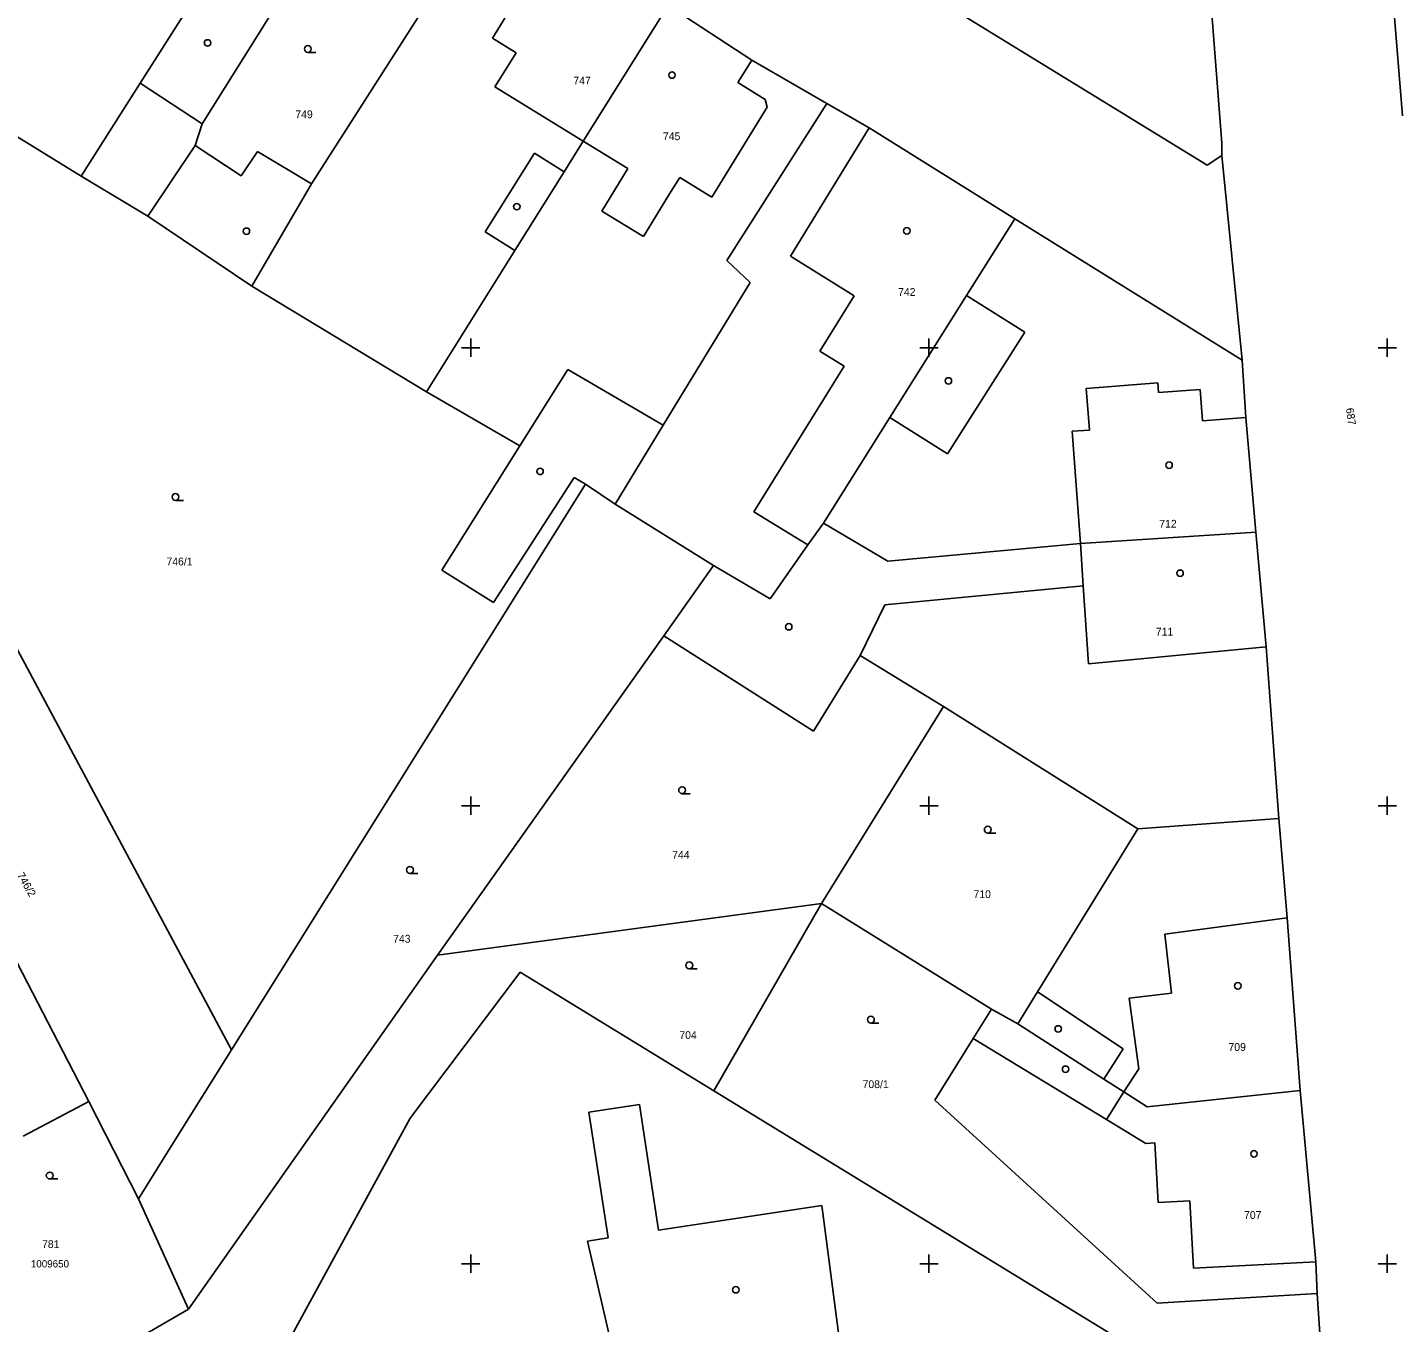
# Model space of a CAD drawing. Extents: x -702257 to -701487, y -1009871 to -1008841.
# Drawn here: x -701799.2 to -701724.3, y -1009653.2 to -1009582.5 of the extents above; entities that cross this region are included whole.
import ezdxf

# ---------------------------------------------------------------- set-up
doc = ezdxf.new("R2010")
doc.units = 0
for name, color, linetype in [('Z_hektometricka_sit', 7, 'Continuous'), ('Z_hektometricka_sit_popis', 7, 'Continuous'), ('Z_katastr_cisla_pozemkova', 7, 'Continuous'), ('Z_katastr_cisla_stavebni', 7, 'Continuous'), ('Z_katastr_hranice', 7, 'Continuous'), ('Z_katastr_vnitrni_kresba', 7, 'Continuous'), ('Z_katastr_znacky_budov', 7, 'Continuous'), ('Z_katastr_znacky_kultur', 7, 'Continuous')]:
    doc.layers.add(name, color=color, linetype=linetype)

msp = doc.modelspace()

# ---------------------------------------------------------------- linework, layer by layer
at = {"layer": 'Z_hektometricka_sit'}
for p, q in [((-701775, -1009599.5), (-701775, -1009600.5)), ((-701775, -1009599.5), (-701775, -1009600.5)), ((-701750, -1009599.5), (-701750, -1009600.5)), ((-701750, -1009599.5), (-701750, -1009600.5)), ((-701725, -1009599.5), (-701725, -1009600.5)), ((-701725, -1009599.5), (-701725, -1009600.5)), ((-701775.5, -1009600), (-701774.5, -1009600)), ((-701775.5, -1009600), (-701774.5, -1009600)), ((-701750.5, -1009600), (-701749.5, -1009600)), ((-701750.5, -1009600), (-701749.5, -1009600)), ((-701725.5, -1009600), (-701724.5, -1009600)), ((-701725.5, -1009600), (-701724.5, -1009600)), ((-701775, -1009624.5), (-701775, -1009625.5)), ((-701775, -1009624.5), (-701775, -1009625.5)), ((-701750, -1009624.5), (-701750, -1009625.5)), ((-701750, -1009624.5), (-701750, -1009625.5)), ((-701725, -1009624.5), (-701725, -1009625.5)), ((-701725, -1009624.5), (-701725, -1009625.5)), ((-701775.5, -1009625), (-701774.5, -1009625)), ((-701775.5, -1009625), (-701774.5, -1009625)), ((-701750.5, -1009625), (-701749.5, -1009625)), ((-701750.5, -1009625), (-701749.5, -1009625)), ((-701725.5, -1009625), (-701724.5, -1009625)), ((-701725.5, -1009625), (-701724.5, -1009625)), ((-701775, -1009649.5), (-701775, -1009650.5)), ((-701775, -1009649.5), (-701775, -1009650.5)), ((-701750, -1009649.5), (-701750, -1009650.5)), ((-701750, -1009649.5), (-701750, -1009650.5)), ((-701725, -1009649.5), (-701725, -1009650.5)), ((-701725, -1009649.5), (-701725, -1009650.5)), ((-701775.5, -1009650), (-701774.5, -1009650)), ((-701775.5, -1009650), (-701774.5, -1009650)), ((-701750.5, -1009650), (-701749.5, -1009650)), ((-701750.5, -1009650), (-701749.5, -1009650)), ((-701725.5, -1009650), (-701724.5, -1009650)), ((-701725.5, -1009650), (-701724.5, -1009650))]:
    msp.add_line(p, q, dxfattribs=at)
at = {"layer": 'Z_katastr_hranice'}
for p, q in [((-701725.75, -1009567.95), (-701724.17, -1009587.34)), ((-701773.82, -1009575.61), (-701783.68, -1009591.06)), ((-701787.72, -1009577.2), (-701793.03, -1009585.56)), ((-701734.87, -1009577.75), (-701734.02, -1009588.83)), ((-701754.01, -1009578.25), (-701734.82, -1009590.03)), ((-701789.65, -1009587.78), (-701785.11, -1009580.52)), ((-701764.23, -1009581.32), (-701768.86, -1009588.72)), ((-701759.67, -1009584.3), (-701764.23, -1009581.32)), ((-701755.58, -1009586.66), (-701759.67, -1009584.3)), ((-701793.03, -1009585.56), (-701796.25, -1009590.63)), ((-701803.43, -1009586.21), (-701796.25, -1009590.63)), ((-701755.58, -1009586.66), (-701761.02, -1009595.24)), ((-701753.27, -1009587.99), (-701755.58, -1009586.66)), ((-701790.03, -1009588.96), (-701789.65, -1009587.78)), ((-701745.32, -1009592.96), (-701753.27, -1009587.99)), ((-701787.53, -1009590.62), (-701790.03, -1009588.96)), ((-701786.64, -1009589.28), (-701787.53, -1009590.62)), ((-701783.68, -1009591.06), (-701786.64, -1009589.28)), ((-701768.86, -1009588.72), (-701769.9, -1009590.39)), ((-701734.02, -1009588.83), (-701734.02, -1009589.5)), ((-701734.82, -1009590.03), (-701734.02, -1009589.5)), ((-701734.02, -1009589.5), (-701732.92, -1009600.67)), ((-701796.25, -1009590.63), (-701792.62, -1009592.81)), ((-701769.9, -1009590.39), (-701772.59, -1009594.69)), ((-701783.68, -1009591.06), (-701786.94, -1009596.63)), ((-701792.62, -1009592.81), (-701786.94, -1009596.63)), ((-701745.32, -1009592.96), (-701747.95, -1009597.14)), ((-701732.92, -1009600.67), (-701745.32, -1009592.96)), ((-701772.59, -1009594.69), (-701777.42, -1009602.4)), ((-701761.02, -1009595.24), (-701759.75, -1009596.44)), ((-701786.94, -1009596.63), (-701777.42, -1009602.4)), ((-701759.75, -1009596.44), (-701764.5, -1009604.23)), ((-701747.95, -1009597.14), (-701752.14, -1009603.81)), ((-701732.92, -1009600.67), (-701732.71, -1009603.81)), ((-701777.42, -1009602.4), (-701772.32, -1009605.36)), ((-701764.5, -1009604.23), (-701767.12, -1009608.53)), ((-701752.14, -1009603.81), (-701755.76, -1009609.57)), ((-701732.71, -1009603.81), (-701732.17, -1009610.07)), ((-701772.32, -1009605.36), (-701776.57, -1009612.14)), ((-701773.75, -1009613.9), (-701769.35, -1009607.08)), ((-701769.35, -1009607.08), (-701768.73, -1009607.44)), ((-701768.73, -1009607.44), (-701788.05, -1009638.33)), ((-701767.12, -1009608.53), (-701768.73, -1009607.44)), ((-701767.12, -1009608.53), (-701761.75, -1009611.88)), ((-701755.76, -1009609.57), (-701756.6, -1009610.76)), ((-701752.25, -1009611.65), (-701755.76, -1009609.57)), ((-701732.17, -1009610.07), (-701741.73, -1009610.69)), ((-701732.17, -1009610.07), (-701731.61, -1009616.32)), ((-701756.6, -1009610.76), (-701758.67, -1009613.71)), ((-701741.73, -1009610.69), (-701752.25, -1009611.65)), ((-701776.57, -1009612.14), (-701773.75, -1009613.9)), ((-701761.75, -1009611.88), (-701764.47, -1009615.72)), ((-701758.67, -1009613.71), (-701761.75, -1009611.88)), ((-701801.79, -1009612.64), (-701788.05, -1009638.33)), ((-701776.81, -1009633.16), (-701764.47, -1009615.72)), ((-701764.47, -1009615.72), (-701756.29, -1009620.92)), ((-701756.29, -1009620.92), (-701753.76, -1009616.79)), ((-701753.76, -1009616.79), (-701749.21, -1009619.59)), ((-701731.61, -1009616.32), (-701730.91, -1009625.7)), ((-701749.21, -1009619.59), (-701755.86, -1009630.34)), ((-701738.6, -1009626.25), (-701749.21, -1009619.59)), ((-701730.91, -1009625.7), (-701738.6, -1009626.25)), ((-701730.91, -1009625.7), (-701730.45, -1009631.11)), ((-701738.6, -1009626.25), (-701744.07, -1009635.15)), ((-701795.84, -1009641.14), (-701801.48, -1009630.24)), ((-701755.86, -1009630.34), (-701776.81, -1009633.16)), ((-701761.73, -1009640.56), (-701755.86, -1009630.34)), ((-701755.86, -1009630.34), (-701746.58, -1009636.11)), ((-701730.45, -1009631.11), (-701729.74, -1009640.54)), ((-701776.81, -1009633.16), (-701790.39, -1009652.48)), ((-701778.31, -1009642.06), (-701772.31, -1009634.08)), ((-701772.31, -1009634.08), (-701761.73, -1009640.56)), ((-701744.07, -1009635.15), (-701745.15, -1009636.91)), ((-701746.58, -1009636.11), (-701747.58, -1009637.71)), ((-701745.15, -1009636.91), (-701746.58, -1009636.11)), ((-701740.46, -1009639.92), (-701745.15, -1009636.91)), ((-701747.58, -1009637.71), (-701749.68, -1009641.07)), ((-701788.05, -1009638.33), (-701791.12, -1009643.23)), ((-701739.36, -1009640.62), (-701740.46, -1009639.92)), ((-701755.08, -1009644.63), (-701761.73, -1009640.56)), ((-701738.09, -1009641.44), (-701739.36, -1009640.62)), ((-701729.74, -1009640.54), (-701738.09, -1009641.44)), ((-701729.74, -1009640.54), (-701728.9, -1009649.89)), ((-701799.41, -1009643.03), (-701795.84, -1009641.14)), ((-701793.13, -1009646.45), (-701795.84, -1009641.14)), ((-701765.79, -1009641.3), (-701768.56, -1009641.72)), ((-701768.56, -1009641.72), (-701767.51, -1009648.59)), ((-701764.75, -1009648.17), (-701765.79, -1009641.3)), ((-701749.68, -1009641.07), (-701737.54, -1009652.15)), ((-701787.31, -1009658.54), (-701778.31, -1009642.06)), ((-701791.12, -1009643.23), (-701793.13, -1009646.45)), ((-701734.43, -1009657.28), (-701755.08, -1009644.63)), ((-701793.13, -1009646.45), (-701790.39, -1009652.48)), ((-701755.85, -1009646.81), (-701764.75, -1009648.17)), ((-701754.4, -1009657.77), (-701755.85, -1009646.81)), ((-701767.51, -1009648.59), (-701768.63, -1009648.76)), ((-701768.63, -1009648.76), (-701766.14, -1009659.47)), ((-701728.9, -1009649.89), (-701728.82, -1009651.63)), ((-701737.54, -1009652.15), (-701728.82, -1009651.63)), ((-701728.82, -1009651.63), (-701728.59, -1009655.17)), ((-701790.39, -1009652.48), (-701797.61, -1009656.65))]:
    msp.add_line(p, q, dxfattribs=at)
at = {"layer": 'Z_katastr_vnitrni_kresba'}
for p, q in [((-701772.59, -1009581.11), (-701773.82, -1009583.1)), ((-701773.82, -1009583.1), (-701772.53, -1009583.9)), ((-701772.53, -1009583.9), (-701773.68, -1009585.76)), ((-701759.67, -1009584.3), (-701760.43, -1009585.53)), ((-701789.65, -1009587.78), (-701793.03, -1009585.56)), ((-701760.43, -1009585.53), (-701758.94, -1009586.45)), ((-701773.68, -1009585.76), (-701768.86, -1009588.72)), ((-701758.82, -1009586.86), (-701761.85, -1009591.78)), ((-701758.94, -1009586.45), (-701758.82, -1009586.86)), ((-701753.27, -1009587.99), (-701757.55, -1009595)), ((-701792.62, -1009592.81), (-701790.03, -1009588.96)), ((-701766.43, -1009590.21), (-701768.86, -1009588.72)), ((-701774.21, -1009593.67), (-701771.52, -1009589.38)), ((-701771.52, -1009589.38), (-701769.9, -1009590.39)), ((-701767.85, -1009592.54), (-701766.43, -1009590.21)), ((-701763.6, -1009590.71), (-701764.15, -1009591.6)), ((-701761.85, -1009591.78), (-701763.6, -1009590.71)), ((-701764.15, -1009591.6), (-701765.57, -1009593.93)), ((-701765.57, -1009593.93), (-701767.85, -1009592.54)), ((-701772.59, -1009594.69), (-701774.21, -1009593.67)), ((-701757.55, -1009595), (-701754.08, -1009597.16)), ((-701754.08, -1009597.16), (-701755.96, -1009600.18)), ((-701747.95, -1009597.14), (-701744.76, -1009599.15)), ((-701744.76, -1009599.15), (-701748.99, -1009605.79)), ((-701755.96, -1009600.18), (-701754.62, -1009601.01)), ((-701772.32, -1009605.36), (-701769.7, -1009601.19)), ((-701769.7, -1009601.19), (-701764.5, -1009604.23)), ((-701754.62, -1009601.01), (-701759.56, -1009608.95)), ((-701737.51, -1009601.92), (-701741.42, -1009602.22)), ((-701737.47, -1009602.44), (-701737.51, -1009601.92)), ((-701741.42, -1009602.22), (-701741.24, -1009604.49)), ((-701735.2, -1009602.27), (-701737.47, -1009602.44)), ((-701735.07, -1009603.98), (-701735.2, -1009602.27)), ((-701748.99, -1009605.79), (-701752.14, -1009603.81)), ((-701732.71, -1009603.81), (-701735.07, -1009603.98)), ((-701741.24, -1009604.49), (-701742.19, -1009604.56)), ((-701742.19, -1009604.56), (-701741.73, -1009610.69)), ((-701759.56, -1009608.95), (-701756.6, -1009610.76)), ((-701741.73, -1009610.69), (-701741.58, -1009612.99)), ((-701741.58, -1009612.99), (-701752.4, -1009614.03)), ((-701741.29, -1009617.25), (-701741.58, -1009612.99)), ((-701753.76, -1009616.79), (-701752.4, -1009614.03)), ((-701731.61, -1009616.32), (-701741.29, -1009617.25)), ((-701730.45, -1009631.11), (-701737.13, -1009632)), ((-701737.13, -1009632), (-701736.76, -1009635.23)), ((-701744.07, -1009635.15), (-701739.4, -1009638.27)), ((-701736.76, -1009635.23), (-701739.08, -1009635.5)), ((-701739.08, -1009635.5), (-701738.55, -1009639.35)), ((-701740.32, -1009642.12), (-701747.58, -1009637.71)), ((-701739.4, -1009638.27), (-701740.46, -1009639.92)), ((-701739.36, -1009640.62), (-701738.55, -1009639.35)), ((-701740.32, -1009642.12), (-701739.36, -1009640.62)), ((-701738.17, -1009643.43), (-701740.32, -1009642.12)), ((-701737.67, -1009643.4), (-701738.17, -1009643.43)), ((-701737.5, -1009646.66), (-701737.67, -1009643.4)), ((-701735.76, -1009646.57), (-701737.5, -1009646.66)), ((-701735.57, -1009650.23), (-701735.76, -1009646.57)), ((-701728.9, -1009649.89), (-701735.57, -1009650.23))]:
    msp.add_line(p, q, dxfattribs=at)
at = {"layer": 'Z_katastr_znacky_budov'}
for centre in [(-701789.357, -1009583.359), (-701764.017, -1009585.119), (-701772.487, -1009592.299), (-701787.237, -1009593.639), (-701751.207, -1009593.619), (-701748.937, -1009601.809), (-701736.897, -1009606.409), (-701771.217, -1009606.749), (-701736.297, -1009612.309), (-701757.647, -1009615.229), (-701733.147, -1009634.829), (-701742.947, -1009637.179), (-701742.547, -1009639.379), (-701732.267, -1009643.999), (-701760.537, -1009651.419)]:
    msp.add_circle(centre, 0.175, dxfattribs=at)
at = {"layer": 'Z_katastr_znacky_kultur'}
for p, q in [((-701783.888, -1009583.88), (-701783.451, -1009583.88)), ((-701791.108, -1009608.33), (-701790.671, -1009608.33)), ((-701763.468, -1009624.34), (-701763.031, -1009624.34)), ((-701746.788, -1009626.49), (-701746.351, -1009626.49)), ((-701778.318, -1009628.69), (-701777.881, -1009628.69)), ((-701763.078, -1009633.9), (-701762.641, -1009633.9)), ((-701753.168, -1009636.86), (-701752.731, -1009636.86)), ((-701797.968, -1009645.37), (-701797.531, -1009645.37))]:
    msp.add_line(p, q, dxfattribs=at)
for centre in [(-701783.888, -1009583.692), (-701791.108, -1009608.142), (-701763.468, -1009624.152), (-701746.788, -1009626.302), (-701778.318, -1009628.502), (-701763.078, -1009633.712), (-701753.168, -1009636.672), (-701797.968, -1009645.182)]:
    msp.add_circle(centre, 0.187, dxfattribs=at)

# ---------------------------------------------------------------- texts
at = {"layer": 'Z_hektometricka_sit_popis'}
msp.add_text('1009650', height=0.4, dxfattribs=at).set_placement((-701799, -1009650.2))
at = {"layer": 'Z_katastr_cisla_pozemkova'}
for s, p in [('749', (-701784.569, -1009587.47)), ('746/1', (-701791.599, -1009611.88)), ('744', (-701764.009, -1009627.89)), ('710', (-701747.569, -1009630.039)), ('743', (-701779.233, -1009632.47)), ('704', (-701763.618, -1009637.73)), ('708/1', (-701753.619, -1009640.41)), ('781', (-701798.389, -1009649.14))]:
    msp.add_text(s, height=0.425, dxfattribs=at).set_placement(p)
for s, rotation, p in [('687', 278, (-701727.253, -1009603.31)), ('746/2', 300, (-701799.772, -1009628.785))]:
    msp.add_text(s, height=0.425, rotation=rotation, dxfattribs=at).set_placement(p)
at = {"layer": 'Z_katastr_cisla_stavebni'}
for s, p in [('747', (-701769.399, -1009585.63)), ('745', (-701764.513, -1009588.669)), ('742', (-701751.683, -1009597.169)), ('712', (-701737.434, -1009609.82)), ('711', (-701737.621, -1009615.71)), ('709', (-701733.658, -1009638.38)), ('707', (-701732.809, -1009647.549))]:
    msp.add_text(s, height=0.425, dxfattribs=at).set_placement(p)

doc.saveas('drawing.dxf')
